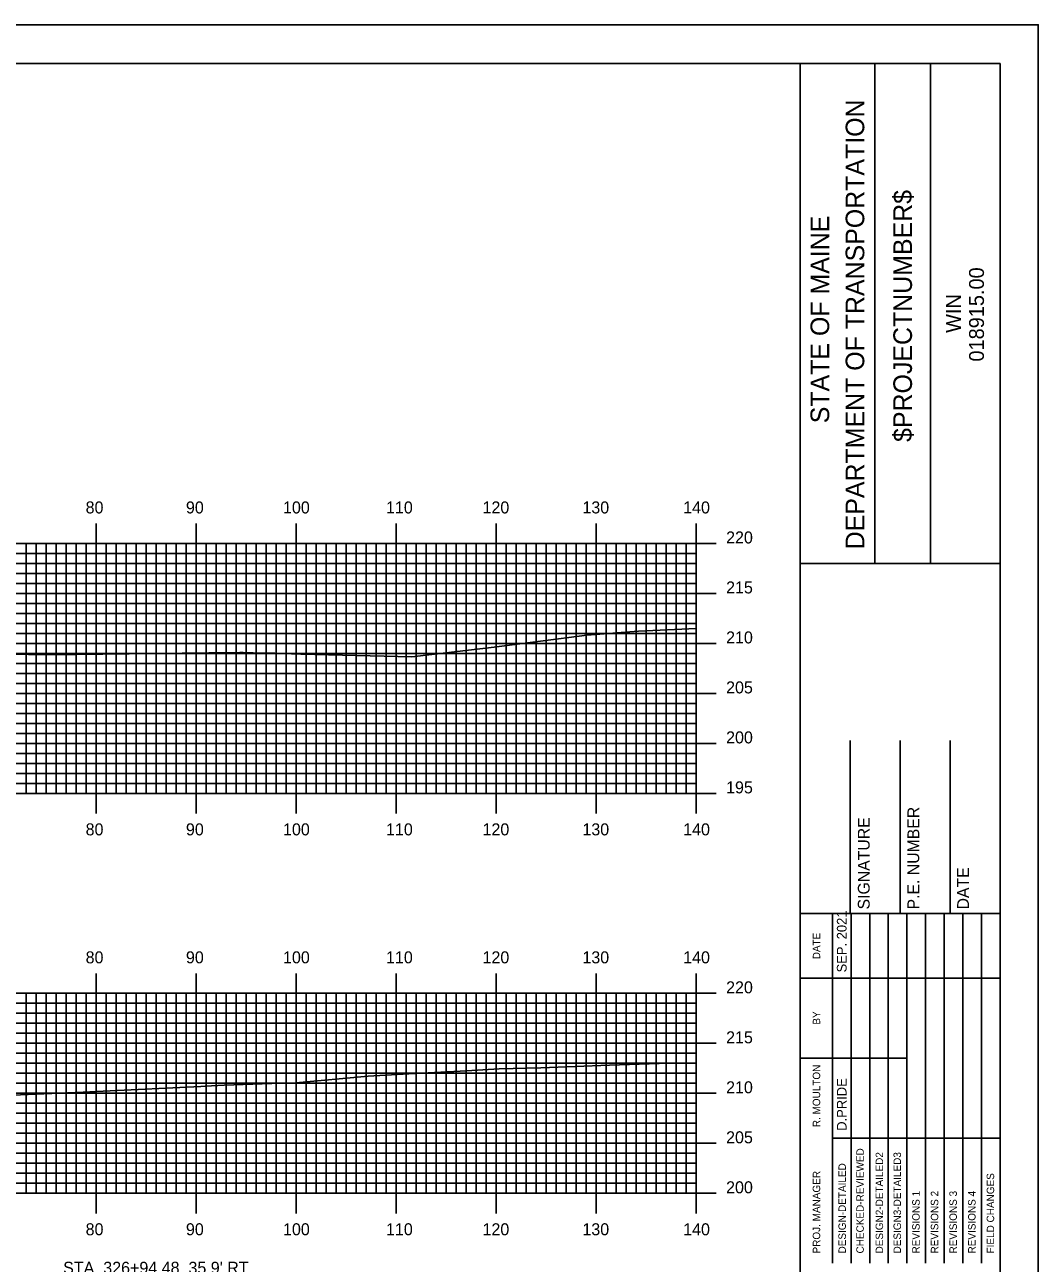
# Model space of a CAD drawing. Extents: x 1821605 to 1821948, y 442591 to 442811.
# Drawn here: x 1821843.6 to 1821945, y 442686.7 to 442810.5 of the extents above; entities that cross this region are included whole.
import ezdxf

# ---------------------------------------------------------------- set-up
doc = ezdxf.new("R2010")
doc.units = 0
for name, color, linetype in [('BORDER', 7, 'Continuous'), ('D_Text_Standard', 7, 'Continuous'), ('H_V ANNOTATION', 7, 'Continuous'), ('MAJOR', 7, 'Continuous'), ('MINOR', 7, 'Continuous'), ('PLOT BOUNDARY', 7, 'Continuous'), ('S_Roadway_Centerline', 7, 'Continuous')]:
    doc.layers.add(name, color=color, linetype=linetype)

msp = doc.modelspace()

# ---------------------------------------------------------------- linework, layer by layer
at = {"layer": 'BORDER'}
for p, q in [((1821921.14, 442596.67), (1821921.14, 442806.67)), ((1821928.6, 442756.66), (1821928.6, 442806.66)), ((1821934.19, 442756.66), (1821934.19, 442806.66)), ((1821921.15, 442756.65), (1821941.14, 442756.65)), ((1821926.14, 442721.67), (1821926.14, 442738.97)), ((1821931.14, 442721.67), (1821931.14, 442738.97)), ((1821936.14, 442721.67), (1821936.14, 442738.97)), ((1821921.14, 442721.67), (1821941.14, 442721.67))]:
    msp.add_line(p, q, dxfattribs=at)
msp.add_lwpolyline([(1821621.14, 442596.67), (1821941.14, 442596.67), (1821941.14, 442806.67), (1821621.14, 442806.67)], close=True, dxfattribs=at)
for points in [[(1821924.37, 442715.17), (1821924.37, 442721.67)], [(1821926.24, 442686.68), (1821926.24, 442721.67)], [(1821928.1, 442721.67), (1821928.1, 442686.68)], [(1821929.96, 442686.68), (1821929.96, 442721.67)], [(1821931.83, 442686.68), (1821931.83, 442721.67)], [(1821933.69, 442686.68), (1821933.69, 442721.67)], [(1821935.55, 442686.68), (1821935.55, 442721.67)], [(1821937.42, 442686.68), (1821937.42, 442721.67)], [(1821939.28, 442686.68), (1821939.28, 442721.67)], [(1821924.37, 442686.68), (1821924.37, 442720.26)], [(1821921.14, 442715.17), (1821941.14, 442715.17)], [(1821921.14, 442707.17), (1821924.37, 442707.17)], [(1821924.37, 442707.17), (1821931.83, 442707.17)], [(1821924.37, 442699.17), (1821941.14, 442699.17)]]:
    msp.add_lwpolyline(points, dxfattribs=at)
at = {"layer": 'MAJOR'}
for p, q in [((1821850.74, 442760.67), (1821850.74, 442758.67)), ((1821860.74, 442760.67), (1821860.74, 442758.67)), ((1821870.74, 442760.67), (1821870.74, 442758.67)), ((1821880.74, 442760.67), (1821880.74, 442758.67)), ((1821890.74, 442760.67), (1821890.74, 442758.67)), ((1821900.74, 442760.67), (1821900.74, 442758.67)), ((1821910.74, 442760.67), (1821910.74, 442758.67)), ((1821630.74, 442758.67), (1821910.74, 442758.67)), ((1821630.74, 442758.67), (1821910.74, 442758.67)), ((1821850.74, 442733.67), (1821850.74, 442758.67)), ((1821860.74, 442733.67), (1821860.74, 442758.67)), ((1821870.74, 442733.67), (1821870.74, 442758.67)), ((1821880.74, 442733.67), (1821880.74, 442758.67)), ((1821890.74, 442733.67), (1821890.74, 442758.67)), ((1821900.74, 442733.67), (1821900.74, 442758.67)), ((1821912.75, 442758.67), (1821908.74, 442758.67)), ((1821910.74, 442733.67), (1821910.74, 442758.67)), ((1821910.74, 442733.67), (1821910.74, 442758.67)), ((1821630.74, 442753.67), (1821910.74, 442753.67)), ((1821912.75, 442753.67), (1821908.74, 442753.67)), ((1821630.74, 442748.67), (1821910.74, 442748.67)), ((1821912.75, 442748.67), (1821908.74, 442748.67)), ((1821630.74, 442743.67), (1821910.74, 442743.67)), ((1821912.75, 442743.67), (1821908.74, 442743.67)), ((1821630.74, 442738.67), (1821910.74, 442738.67)), ((1821912.75, 442738.67), (1821908.74, 442738.67)), ((1821630.74, 442733.67), (1821910.74, 442733.67)), ((1821630.74, 442733.67), (1821910.74, 442733.67)), ((1821850.74, 442731.66), (1821850.74, 442733.67)), ((1821860.74, 442731.66), (1821860.74, 442733.67)), ((1821870.74, 442731.66), (1821870.74, 442733.67)), ((1821880.74, 442731.66), (1821880.74, 442733.67)), ((1821890.74, 442731.66), (1821890.74, 442733.67)), ((1821900.74, 442731.66), (1821900.74, 442733.67)), ((1821912.75, 442733.67), (1821908.74, 442733.67)), ((1821910.74, 442731.66), (1821910.74, 442733.67)), ((1821850.74, 442715.67), (1821850.74, 442713.67)), ((1821860.74, 442715.67), (1821860.74, 442713.67)), ((1821870.74, 442715.67), (1821870.74, 442713.67)), ((1821880.74, 442715.67), (1821880.74, 442713.67)), ((1821890.74, 442715.67), (1821890.74, 442713.67)), ((1821900.74, 442715.67), (1821900.74, 442713.67)), ((1821910.74, 442715.67), (1821910.74, 442713.67)), ((1821770.74, 442713.67), (1821910.74, 442713.67)), ((1821770.74, 442713.67), (1821910.74, 442713.67)), ((1821850.74, 442693.67), (1821850.74, 442713.67)), ((1821860.74, 442693.67), (1821860.74, 442713.67)), ((1821870.74, 442693.67), (1821870.74, 442713.67)), ((1821880.74, 442693.67), (1821880.74, 442713.67)), ((1821890.74, 442693.67), (1821890.74, 442713.67)), ((1821900.74, 442693.67), (1821900.74, 442713.67)), ((1821912.75, 442713.67), (1821908.74, 442713.67)), ((1821910.74, 442693.67), (1821910.74, 442713.67)), ((1821910.74, 442693.67), (1821910.74, 442713.67)), ((1821770.74, 442708.67), (1821910.74, 442708.67)), ((1821912.75, 442708.67), (1821908.74, 442708.67)), ((1821770.74, 442703.67), (1821910.74, 442703.67)), ((1821912.75, 442703.67), (1821908.74, 442703.67)), ((1821770.74, 442698.67), (1821910.74, 442698.67)), ((1821912.75, 442698.67), (1821908.74, 442698.67)), ((1821770.74, 442693.67), (1821910.74, 442693.67)), ((1821770.74, 442693.67), (1821910.74, 442693.67)), ((1821850.74, 442691.66), (1821850.74, 442693.67)), ((1821860.74, 442691.66), (1821860.74, 442693.67)), ((1821870.74, 442691.66), (1821870.74, 442693.67)), ((1821880.74, 442691.66), (1821880.74, 442693.67)), ((1821890.74, 442691.66), (1821890.74, 442693.67)), ((1821900.74, 442691.66), (1821900.74, 442693.67)), ((1821912.75, 442693.67), (1821908.74, 442693.67)), ((1821910.74, 442691.66), (1821910.74, 442693.67))]:
    msp.add_line(p, q, dxfattribs=at)
at = {"layer": 'MINOR'}
for p, q in [((1821843.74, 442733.67), (1821843.74, 442758.67)), ((1821844.74, 442733.67), (1821844.74, 442758.67)), ((1821845.74, 442733.67), (1821845.74, 442758.67)), ((1821846.74, 442733.67), (1821846.74, 442758.67)), ((1821847.74, 442733.67), (1821847.74, 442758.67)), ((1821848.74, 442733.67), (1821848.74, 442758.67)), ((1821849.74, 442733.67), (1821849.74, 442758.67)), ((1821851.74, 442733.67), (1821851.74, 442758.67)), ((1821852.74, 442733.67), (1821852.74, 442758.67)), ((1821853.74, 442733.67), (1821853.74, 442758.67)), ((1821854.74, 442733.67), (1821854.74, 442758.67)), ((1821855.74, 442733.67), (1821855.74, 442758.67)), ((1821856.74, 442733.67), (1821856.74, 442758.67)), ((1821857.74, 442733.67), (1821857.74, 442758.67)), ((1821858.74, 442733.67), (1821858.74, 442758.67)), ((1821859.74, 442733.67), (1821859.74, 442758.67)), ((1821861.74, 442733.67), (1821861.74, 442758.67)), ((1821862.74, 442733.67), (1821862.74, 442758.67)), ((1821863.74, 442733.67), (1821863.74, 442758.67)), ((1821864.74, 442733.67), (1821864.74, 442758.67)), ((1821865.74, 442733.67), (1821865.74, 442758.67)), ((1821866.74, 442733.67), (1821866.74, 442758.67)), ((1821867.74, 442733.67), (1821867.74, 442758.67)), ((1821868.74, 442733.67), (1821868.74, 442758.67)), ((1821869.74, 442733.67), (1821869.74, 442758.67)), ((1821871.74, 442733.67), (1821871.74, 442758.67)), ((1821872.74, 442733.67), (1821872.74, 442758.67)), ((1821873.74, 442733.67), (1821873.74, 442758.67)), ((1821874.74, 442733.67), (1821874.74, 442758.67)), ((1821875.74, 442733.67), (1821875.74, 442758.67)), ((1821876.74, 442733.67), (1821876.74, 442758.67)), ((1821877.74, 442733.67), (1821877.74, 442758.67)), ((1821878.74, 442733.67), (1821878.74, 442758.67)), ((1821879.74, 442733.67), (1821879.74, 442758.67)), ((1821881.74, 442733.67), (1821881.74, 442758.67)), ((1821882.74, 442733.67), (1821882.74, 442758.67)), ((1821883.74, 442733.67), (1821883.74, 442758.67)), ((1821884.74, 442733.67), (1821884.74, 442758.67)), ((1821885.74, 442733.67), (1821885.74, 442758.67)), ((1821886.74, 442733.67), (1821886.74, 442758.67)), ((1821887.74, 442733.67), (1821887.74, 442758.67)), ((1821888.74, 442733.67), (1821888.74, 442758.67)), ((1821889.74, 442733.67), (1821889.74, 442758.67)), ((1821891.74, 442733.67), (1821891.74, 442758.67)), ((1821892.74, 442733.67), (1821892.74, 442758.67)), ((1821893.74, 442733.67), (1821893.74, 442758.67)), ((1821894.74, 442733.67), (1821894.74, 442758.67)), ((1821895.74, 442733.67), (1821895.74, 442758.67)), ((1821896.74, 442733.67), (1821896.74, 442758.67)), ((1821897.74, 442733.67), (1821897.74, 442758.67)), ((1821898.74, 442733.67), (1821898.74, 442758.67)), ((1821899.74, 442733.67), (1821899.74, 442758.67)), ((1821901.74, 442733.67), (1821901.74, 442758.67)), ((1821902.74, 442733.67), (1821902.74, 442758.67)), ((1821903.74, 442733.67), (1821903.74, 442758.67)), ((1821904.74, 442733.67), (1821904.74, 442758.67)), ((1821905.74, 442733.67), (1821905.74, 442758.67)), ((1821906.74, 442733.67), (1821906.74, 442758.67)), ((1821907.74, 442733.67), (1821907.74, 442758.67)), ((1821908.74, 442733.67), (1821908.74, 442758.67)), ((1821909.74, 442733.67), (1821909.74, 442758.67)), ((1821630.74, 442757.67), (1821910.74, 442757.67)), ((1821910.74, 442757.67), (1821908.74, 442757.67)), ((1821630.74, 442756.67), (1821910.74, 442756.67)), ((1821910.74, 442756.67), (1821908.74, 442756.67)), ((1821630.74, 442755.67), (1821910.74, 442755.67)), ((1821910.74, 442755.67), (1821908.74, 442755.67)), ((1821630.74, 442754.67), (1821910.74, 442754.67)), ((1821910.74, 442754.67), (1821908.74, 442754.67)), ((1821630.74, 442752.67), (1821910.74, 442752.67)), ((1821910.74, 442752.67), (1821908.74, 442752.67)), ((1821630.74, 442751.67), (1821910.74, 442751.67)), ((1821910.74, 442751.67), (1821908.74, 442751.67)), ((1821630.74, 442750.67), (1821910.74, 442750.67)), ((1821910.74, 442750.67), (1821908.74, 442750.67)), ((1821630.74, 442749.67), (1821910.74, 442749.67)), ((1821910.74, 442749.67), (1821908.74, 442749.67)), ((1821630.74, 442747.67), (1821910.74, 442747.67)), ((1821910.74, 442747.67), (1821908.74, 442747.67)), ((1821630.74, 442746.67), (1821910.74, 442746.67)), ((1821910.74, 442746.67), (1821908.74, 442746.67)), ((1821630.74, 442745.67), (1821910.74, 442745.67)), ((1821910.74, 442745.67), (1821908.74, 442745.67)), ((1821630.74, 442744.67), (1821910.74, 442744.67)), ((1821910.74, 442744.67), (1821908.74, 442744.67)), ((1821630.74, 442742.67), (1821910.74, 442742.67)), ((1821910.74, 442742.67), (1821908.74, 442742.67)), ((1821630.74, 442741.67), (1821910.74, 442741.67)), ((1821910.74, 442741.67), (1821908.74, 442741.67)), ((1821630.74, 442740.67), (1821910.74, 442740.67)), ((1821910.74, 442740.67), (1821908.74, 442740.67)), ((1821630.74, 442739.67), (1821910.74, 442739.67)), ((1821910.74, 442739.67), (1821908.74, 442739.67)), ((1821630.74, 442737.67), (1821910.74, 442737.67)), ((1821910.74, 442737.67), (1821908.74, 442737.67)), ((1821630.74, 442736.67), (1821910.74, 442736.67)), ((1821910.74, 442736.67), (1821908.74, 442736.67)), ((1821630.74, 442735.67), (1821910.74, 442735.67)), ((1821910.74, 442735.67), (1821908.74, 442735.67)), ((1821630.74, 442734.67), (1821910.74, 442734.67)), ((1821910.74, 442734.67), (1821908.74, 442734.67)), ((1821843.74, 442693.67), (1821843.74, 442713.67)), ((1821844.74, 442693.67), (1821844.74, 442713.67)), ((1821845.74, 442693.67), (1821845.74, 442713.67)), ((1821846.74, 442693.67), (1821846.74, 442713.67)), ((1821847.74, 442693.67), (1821847.74, 442713.67)), ((1821848.74, 442693.67), (1821848.74, 442713.67)), ((1821849.74, 442693.67), (1821849.74, 442713.67)), ((1821851.74, 442693.67), (1821851.74, 442713.67)), ((1821852.74, 442693.67), (1821852.74, 442713.67)), ((1821853.74, 442693.67), (1821853.74, 442713.67)), ((1821854.74, 442693.67), (1821854.74, 442713.67)), ((1821855.74, 442693.67), (1821855.74, 442713.67)), ((1821856.74, 442693.67), (1821856.74, 442713.67)), ((1821857.74, 442693.67), (1821857.74, 442713.67)), ((1821858.74, 442693.67), (1821858.74, 442713.67)), ((1821859.74, 442693.67), (1821859.74, 442713.67)), ((1821861.74, 442693.67), (1821861.74, 442713.67)), ((1821862.74, 442693.67), (1821862.74, 442713.67)), ((1821863.74, 442693.67), (1821863.74, 442713.67)), ((1821864.74, 442693.67), (1821864.74, 442713.67)), ((1821865.74, 442693.67), (1821865.74, 442713.67)), ((1821866.74, 442693.67), (1821866.74, 442713.67)), ((1821867.74, 442693.67), (1821867.74, 442713.67)), ((1821868.74, 442693.67), (1821868.74, 442713.67)), ((1821869.74, 442693.67), (1821869.74, 442713.67)), ((1821871.74, 442693.67), (1821871.74, 442713.67)), ((1821872.74, 442693.67), (1821872.74, 442713.67)), ((1821873.74, 442693.67), (1821873.74, 442713.67)), ((1821874.74, 442693.67), (1821874.74, 442713.67)), ((1821875.74, 442693.67), (1821875.74, 442713.67)), ((1821876.74, 442693.67), (1821876.74, 442713.67)), ((1821877.74, 442693.67), (1821877.74, 442713.67)), ((1821878.74, 442693.67), (1821878.74, 442713.67)), ((1821879.74, 442693.67), (1821879.74, 442713.67)), ((1821881.74, 442693.67), (1821881.74, 442713.67)), ((1821882.74, 442693.67), (1821882.74, 442713.67)), ((1821883.74, 442693.67), (1821883.74, 442713.67)), ((1821884.74, 442693.67), (1821884.74, 442713.67)), ((1821885.74, 442693.67), (1821885.74, 442713.67)), ((1821886.74, 442693.67), (1821886.74, 442713.67)), ((1821887.74, 442693.67), (1821887.74, 442713.67)), ((1821888.74, 442693.67), (1821888.74, 442713.67)), ((1821889.74, 442693.67), (1821889.74, 442713.67)), ((1821891.74, 442693.67), (1821891.74, 442713.67)), ((1821892.74, 442693.67), (1821892.74, 442713.67)), ((1821893.74, 442693.67), (1821893.74, 442713.67)), ((1821894.74, 442693.67), (1821894.74, 442713.67)), ((1821895.74, 442693.67), (1821895.74, 442713.67)), ((1821896.74, 442693.67), (1821896.74, 442713.67)), ((1821897.74, 442693.67), (1821897.74, 442713.67)), ((1821898.74, 442693.67), (1821898.74, 442713.67)), ((1821899.74, 442693.67), (1821899.74, 442713.67)), ((1821901.74, 442693.67), (1821901.74, 442713.67)), ((1821902.74, 442693.67), (1821902.74, 442713.67)), ((1821903.74, 442693.67), (1821903.74, 442713.67)), ((1821904.74, 442693.67), (1821904.74, 442713.67)), ((1821905.74, 442693.67), (1821905.74, 442713.67)), ((1821906.74, 442693.67), (1821906.74, 442713.67)), ((1821907.74, 442693.67), (1821907.74, 442713.67)), ((1821908.74, 442693.67), (1821908.74, 442713.67)), ((1821909.74, 442693.67), (1821909.74, 442713.67)), ((1821770.74, 442712.67), (1821910.74, 442712.67)), ((1821770.74, 442711.67), (1821910.74, 442711.67)), ((1821910.74, 442712.67), (1821908.74, 442712.67)), ((1821910.74, 442711.67), (1821908.74, 442711.67)), ((1821770.74, 442710.67), (1821910.74, 442710.67)), ((1821910.74, 442710.67), (1821908.74, 442710.67)), ((1821770.74, 442709.67), (1821910.74, 442709.67)), ((1821910.74, 442709.67), (1821908.74, 442709.67)), ((1821770.74, 442707.67), (1821910.74, 442707.67)), ((1821770.74, 442706.67), (1821910.74, 442706.67)), ((1821910.74, 442707.67), (1821908.74, 442707.67)), ((1821910.74, 442706.67), (1821908.74, 442706.67)), ((1821770.74, 442705.67), (1821910.74, 442705.67)), ((1821910.74, 442705.67), (1821908.74, 442705.67)), ((1821770.74, 442704.67), (1821910.74, 442704.67)), ((1821910.74, 442704.67), (1821908.74, 442704.67)), ((1821770.74, 442702.67), (1821910.74, 442702.67)), ((1821770.74, 442701.67), (1821910.74, 442701.67)), ((1821910.74, 442702.67), (1821908.74, 442702.67)), ((1821910.74, 442701.67), (1821908.74, 442701.67)), ((1821770.74, 442700.67), (1821910.74, 442700.67)), ((1821910.74, 442700.67), (1821908.74, 442700.67)), ((1821770.74, 442699.67), (1821910.74, 442699.67)), ((1821910.74, 442699.67), (1821908.74, 442699.67)), ((1821770.74, 442697.67), (1821910.74, 442697.67)), ((1821770.74, 442696.67), (1821910.74, 442696.67)), ((1821910.74, 442697.67), (1821908.74, 442697.67)), ((1821910.74, 442696.67), (1821908.74, 442696.67)), ((1821770.74, 442695.67), (1821910.74, 442695.67)), ((1821910.74, 442695.67), (1821908.74, 442695.67)), ((1821770.74, 442694.67), (1821910.74, 442694.67)), ((1821910.74, 442694.67), (1821908.74, 442694.67))]:
    msp.add_line(p, q, dxfattribs=at)
at = {"layer": 'PLOT BOUNDARY'}
msp.add_lwpolyline([(1821604.96, 442590.55), (1821944.96, 442590.55), (1821944.96, 442810.55), (1821604.96, 442810.55)], close=True, dxfattribs=at)
at = {"layer": 'S_Roadway_Centerline'}
for points in [[(1821831.81, 442747.68), (1821843.99, 442747.57), (1821848.74, 442747.57), (1821862, 442747.72), (1821865.1, 442747.77), (1821865.46, 442747.77), (1821867.45, 442747.71), (1821868.62, 442747.68), (1821870.27, 442747.64), (1821871.2, 442747.58), (1821882.3, 442747.33), (1821890.54, 442748.3), (1821899.82, 442749.51), (1821904.98, 442749.89), (1821910.74, 442750.16)], [(1821842.36, 442703.5), (1821849.46, 442703.8), (1821851.44, 442703.89), (1821861.2, 442704.36), (1821861.63, 442704.38), (1821863.56, 442704.49), (1821868.31, 442704.65), (1821870.72, 442704.73), (1821877.93, 442705.37), (1821882, 442705.61), (1821887.78, 442705.91), (1821891.05, 442706.11), (1821895.22, 442706.23), (1821902.08, 442706.48), (1821908.05, 442706.69), (1821910.74, 442706.72)]]:
    msp.add_lwpolyline(points, dxfattribs=at)

# ---------------------------------------------------------------- texts
at = {"layer": 'BORDER'}
for s, height, p in [('DEPARTMENT OF TRANSPORTATION', 1.8635, (1821927.56, 442758.08)), ('$PROJECTNUMBER$', 1.8635, (1821932.33, 442768.82)), ('STATE OF MAINE', 1.8635, (1821924.05, 442770.69)), ('018915.00', 1.491, (1821939.53, 442776.86)), ('WIN', 1.491, (1821937.22, 442779.73)), ('P.E. NUMBER', 1.1811, (1821933.06, 442722.06)), ('SIGNATURE', 1.181, (1821928.1, 442722.06)), ('DATE', 1.181, (1821938.03, 442722.06)), ('SEP. 2021', 0.969, (1821925.79, 442715.76)), ('DATE', 0.743, (1821923.15, 442717.08)), ('BY', 0.743, (1821923.15, 442710.54)), ('R. MOULTON', 0.745, (1821923.15, 442700.28)), ('D.PRIDE', 0.969, (1821925.79, 442699.92)), ('CHECKED-REVIEWED', 0.7455, (1821927.51, 442687.65)), ('DESIGN2-DETAILED2', 0.7455, (1821929.44, 442687.65)), ('DESIGN3-DETAILED3', 0.7455, (1821931.23, 442687.65)), ('PROJ. MANAGER', 0.7455, (1821923.15, 442687.65)), ('DESIGN-DETAILED', 0.7455, (1821925.72, 442687.65)), ('FIELD CHANGES', 0.7455, (1821940.55, 442687.65)), ('REVISIONS 1', 0.7455, (1821933.1, 442687.65)), ('REVISIONS 2', 0.7455, (1821934.96, 442687.65)), ('REVISIONS 3', 0.7455, (1821936.82, 442687.65)), ('REVISIONS 4', 0.7455, (1821938.69, 442687.65))]:
    msp.add_text(s, height=height, rotation=90, dxfattribs=at).set_placement(p)
at = {"layer": 'D_Text_Standard'}
msp.add_text("STA. 326+94.48, 35.9' RT.", height=1.2, dxfattribs=at).set_placement((1821847.44, 442685.62))
at = {"layer": 'H_V ANNOTATION'}
for s, p in [('80', (1821849.69, 442761.67)), ('90', (1821859.72, 442761.67)), ('100', (1821869.43, 442761.67)), ('110', (1821879.73, 442761.67)), ('120', (1821889.38, 442761.67)), ('130', (1821899.37, 442761.67)), ('140', (1821909.45, 442761.67)), ('220', (1821913.74, 442758.67)), ('215', (1821913.74, 442753.67)), ('210', (1821913.74, 442748.67)), ('205', (1821913.74, 442743.67)), ('200', (1821913.74, 442738.67)), ('195', (1821913.74, 442733.67)), ('80', (1821849.69, 442729.47)), ('90', (1821859.72, 442729.47)), ('100', (1821869.43, 442729.47)), ('110', (1821879.73, 442729.47)), ('120', (1821889.38, 442729.47)), ('130', (1821899.37, 442729.47)), ('140', (1821909.45, 442729.47)), ('80', (1821849.69, 442716.67)), ('90', (1821859.72, 442716.67)), ('100', (1821869.43, 442716.67)), ('110', (1821879.73, 442716.67)), ('120', (1821889.38, 442716.67)), ('130', (1821899.37, 442716.67)), ('140', (1821909.45, 442716.67)), ('220', (1821913.74, 442713.67)), ('215', (1821913.74, 442708.67)), ('210', (1821913.74, 442703.67)), ('205', (1821913.74, 442698.67)), ('200', (1821913.74, 442693.67)), ('80', (1821849.69, 442689.47)), ('90', (1821859.72, 442689.47)), ('100', (1821869.43, 442689.47)), ('110', (1821879.73, 442689.47)), ('120', (1821889.38, 442689.47)), ('130', (1821899.37, 442689.47)), ('140', (1821909.45, 442689.47))]:
    msp.add_text(s, height=1.2, dxfattribs=at).set_placement(p)

doc.saveas('drawing.dxf')
